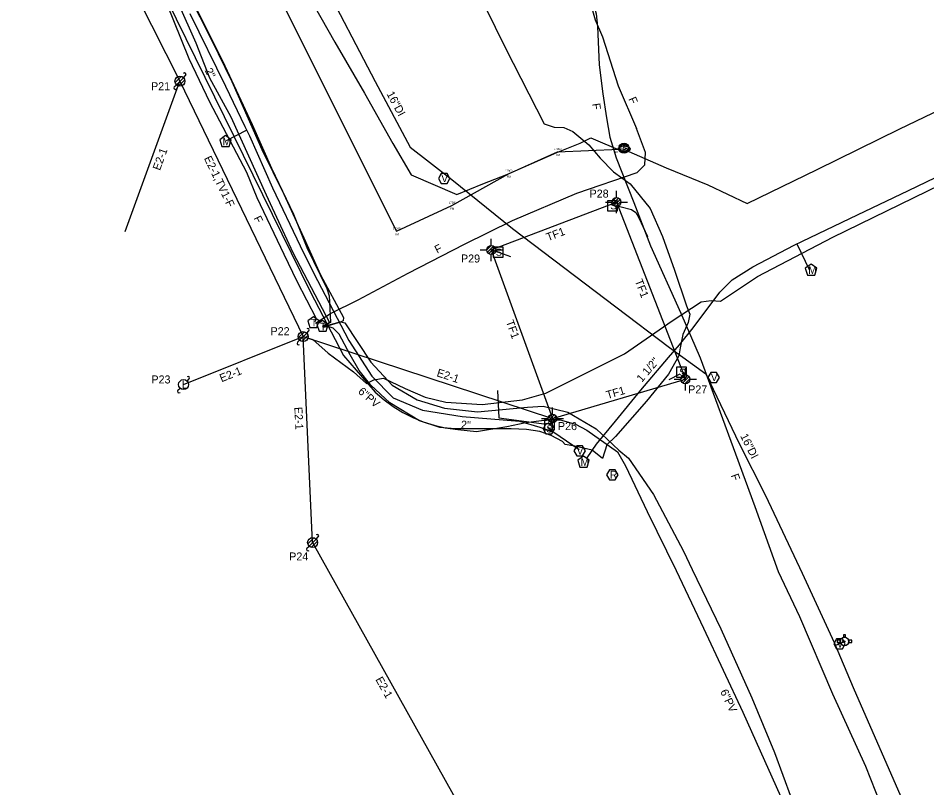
# Model space of a CAD drawing. Extents: x 1614474 to 1865144, y 1098877 to 1212550.
# Drawn here: x 1755531 to 1755984.8, y 1168201.1 to 1168585.7 of the extents above; entities that cross this region are included whole.
import ezdxf

# ---------------------------------------------------------------- set-up
doc = ezdxf.new("R2010")
doc.units = 0
for name, color, linetype in [('RD_EX_SU_H2O', 7, 'Continuous'), ('RD_EX_SU_Ovhd', 7, 'Continuous'), ('RD_EX_SU_Pole', 7, 'Continuous'), ('RD_EX_SU_Sewer', 7, 'Continuous'), ('RD_EX_SU_Telecom', 7, 'Continuous'), ('RD_EX_SU_Trfc', 7, 'Continuous'), ('RD_EX_SU_TX_H2O', 7, 'Continuous'), ('RD_EX_SU_TX_Pole', 7, 'Continuous'), ('RD_EX_SU_TX_Sewer', 7, 'Continuous'), ('RD_EX_SU_TX_Telecom', 7, 'Continuous'), ('RD_EX_UT_txCode', 7, 'Continuous'), ('RD_EX_VEG_txCode', 7, 'Continuous'), ('RD_SMD_Locator', 7, 'Continuous')]:
    doc.layers.add(name, color=color, linetype=linetype)

# ---------------------------------------------------------------- blocks, each defined once
blk = doc.blocks.new('SUE_SMH')
at = {"layer": 'RD_EX_SU_Sewer'}
blk.add_circle((0, 0), 2.5, dxfattribs=at)
blk.add_text('S', height=3.57, dxfattribs=at).set_placement((-1.1, -1.79))
blk = doc.blocks.new('SUE_WFH')
at = {"layer": 'RD_EX_SU_H2O'}
for p, q in [((-2.01, 0.6), (-3.65, 0.6)), ((-3.65, 0.6), (-3.65, -0.45)), ((-0.48, 3.38), (-0.48, 2.04)), ((0.57, 3.38), (-0.48, 3.38)), ((0.57, 2.02), (0.57, 3.38)), ((3.7, 0.6), (2.01, 0.6)), ((3.7, -0.45), (3.7, 0.6)), ((-3.65, -0.45), (-2.05, -0.45)), ((2.05, -0.45), (3.7, -0.45))]:
    blk.add_line(p, q, dxfattribs=at)
for radius in [2.1, 0.263]:
    blk.add_circle((0, 0), radius, dxfattribs=at)
for start, end in [(163.3387, 192.315), (74.2455, 103.2128), (347.685, 16.6613)]:
    blk.add_arc((0, 0), 2.1, start, end, dxfattribs=at)
blk = doc.blocks.new('SUE_WV')
at = {"layer": 'RD_EX_SU_H2O'}
blk.add_lwpolyline([(2.89, 0), (1.44, 2.5), (-1.44, 2.5), (-2.89, 0), (-1.44, -2.5), (1.44, -2.5)], close=True, dxfattribs=at)
blk.add_text('V', height=3.75, dxfattribs=at).set_placement((-1.43, -1.88))

msp = doc.modelspace()

# ---------------------------------------------------------------- linework, layer by layer
at = {"layer": 'RD_EX_SU_H2O'}
for p, q in [((1755635.04, 1168524.51), (1755645.11, 1168529.78)), ((1755919.85, 1168472.87), (1755926.01, 1168460.03)), ((1755943.15, 1168273.87), (1755939.17, 1168272.13))]:
    msp.add_line(p, q, dxfattribs=at)
for points in [[(1755385.42, 1169098.44), (1755401.32, 1169066.46), (1755415.89, 1169036.4), (1755422.95, 1169020.76), (1755426.26, 1169009.34), (1755463.14, 1168972.48), (1755499.82, 1168933.69), (1755512.6, 1168909), (1755538.91, 1168856.4), (1755564.45, 1168803.54), (1755584.77, 1168764.26), (1755602.59, 1168754.78), (1755634.52, 1168695.09), (1755648.65, 1168669.94), (1755682.22, 1168606.15), (1755709.26, 1168554.06), (1755726.87, 1168521.3)], [(1755616.79, 1168588.07), (1755634.63, 1168551.68), (1755644.21, 1168531.62), (1755646.53, 1168526.85), (1755658.08, 1168500.86), (1755671.83, 1168471.89), (1755678.5, 1168458.37), (1755696.16, 1168424.57), (1755707.62, 1168406.78), (1755718.29, 1168395.98), (1755732.94, 1168389.76), (1755752.68, 1168386.64), (1755781.36, 1168384.25), (1755791.61, 1168381.24), (1755798.5, 1168378.79), (1755811.16, 1168370.13)], [(1755726.87, 1168521.3), (1755747.63, 1168505.06), (1755777.82, 1168480.62), (1755829.49, 1168441.52), (1755856.27, 1168421.17), (1755874.43, 1168407.88), (1755891.14, 1168373.18), (1755904.2, 1168347.14)], [(1755815.25, 1168366.07), (1755819.84, 1168372.8), (1755829.29, 1168384.27), (1755841.99, 1168399.77), (1755855.87, 1168416.06), (1755861.36, 1168422.49), (1755868.12, 1168430.87), (1755881.49, 1168448.74), (1755887.6, 1168454.86), (1755897.94, 1168461.44), (1755918.53, 1168472.25), (1755922.78, 1168474.28), (1755950.16, 1168487.37), (1755975.7, 1168499.57), (1756003.04, 1168512.76)], [(1755904.2, 1168347.14), (1755922.61, 1168308.3), (1755938.52, 1168273.68), (1755948, 1168251.19), (1755972.99, 1168194.09), (1755995.27, 1168140.77), (1756050.84, 1167988.86), (1756081.08, 1167905.61), (1756101.58, 1167855.44), (1756116.98, 1167816.66), (1756140.78, 1167753.22), (1756156.44, 1167713.09), (1756172.97, 1167668.41), (1756185.91, 1167635.6), (1756220.9, 1167543.58)]]:
    msp.add_lwpolyline(points, dxfattribs=at)
for points in [[(1755634.55, 1168527.07), (1755631.64, 1168524.96), (1755632.75, 1168521.55), (1755636.34, 1168521.55), (1755637.45, 1168524.96)], [(1755746.64, 1168505.62), (1755745.2, 1168508.12), (1755742.31, 1168508.12), (1755740.87, 1168505.62), (1755742.31, 1168503.12), (1755745.2, 1168503.12)], [(1755927.04, 1168462.79), (1755924.14, 1168460.69), (1755925.25, 1168457.28), (1755928.83, 1168457.28), (1755929.94, 1168460.69)], [(1755881.31, 1168406.21), (1755879.87, 1168408.71), (1755876.98, 1168408.71), (1755875.54, 1168406.21), (1755876.98, 1168403.71), (1755879.87, 1168403.71)], [(1755814.29, 1168369.49), (1755812.85, 1168371.99), (1755809.96, 1168371.99), (1755808.52, 1168369.49), (1755809.96, 1168366.99), (1755812.85, 1168366.99)], [(1755813.37, 1168366.89), (1755810.46, 1168364.79), (1755811.57, 1168361.38), (1755815.16, 1168361.38), (1755816.27, 1168364.79)]]:
    msp.add_lwpolyline(points, close=True, dxfattribs=at)
at = {"layer": 'RD_EX_SU_Ovhd'}
for p, q in [((1755499.08, 1168777.54), (1755611.8, 1168554.19)), ((1755584.39, 1168479.07), (1755611.8, 1168554.19)), ((1755611.8, 1168554.19), (1755673.33, 1168426.55)), ((1755767.32, 1168469.86), (1755829.82, 1168493.82)), ((1755829.82, 1168493.82), (1755864.24, 1168405.22)), ((1755767.32, 1168469.86), (1755797.9, 1168385.65)), ((1755613.6, 1168402.59), (1755673.33, 1168426.55)), ((1755678.06, 1168323.63), (1755673.33, 1168426.55)), ((1755673.33, 1168426.55), (1755797.9, 1168385.65)), ((1755797.9, 1168385.65), (1755864.24, 1168405.22)), ((1755678.06, 1168323.63), (1755772.38, 1168154.45))]:
    msp.add_line(p, q, dxfattribs=at)
at = {"layer": 'RD_EX_SU_Pole'}
for p, q in [((1755609.38, 1168553.54), (1755612.45, 1168556.6)), ((1755610.03, 1168552.42), (1755613.57, 1168555.95)), ((1755611.15, 1168551.77), (1755614.21, 1168554.83)), ((1755613.57, 1168555.95), (1755614.63, 1168557.01)), ((1755608.97, 1168551.36), (1755610.03, 1168552.42)), ((1755827.61, 1168493.96), (1755829.69, 1168496.04)), ((1755827.86, 1168492.8), (1755830.85, 1168495.78)), ((1755829.82, 1168496.04), (1755829.82, 1168499.35)), ((1755824.3, 1168493.82), (1755827.6, 1168493.82)), ((1755828.51, 1168492.04), (1755831.61, 1168495.13)), ((1755829.52, 1168491.63), (1755832.02, 1168494.12)), ((1755829.82, 1168488.3), (1755829.82, 1168491.61)), ((1755832.04, 1168493.82), (1755835.34, 1168493.82)), ((1755767.32, 1168472.08), (1755767.32, 1168475.39)), ((1755761.8, 1168469.86), (1755765.11, 1168469.86)), ((1755765.11, 1168469.99), (1755767.2, 1168472.07)), ((1755765.36, 1168468.83), (1755768.36, 1168471.82)), ((1755766.01, 1168468.07), (1755769.12, 1168471.16)), ((1755767.02, 1168467.66), (1755769.52, 1168470.15)), ((1755769.54, 1168469.86), (1755772.85, 1168469.86)), ((1755767.32, 1168464.33), (1755767.32, 1168467.64)), ((1755670.91, 1168425.91), (1755673.98, 1168428.97)), ((1755671.56, 1168424.79), (1755675.1, 1168428.32)), ((1755675.1, 1168428.32), (1755676.16, 1168429.38)), ((1755670.5, 1168423.73), (1755671.56, 1168424.79)), ((1755672.68, 1168424.14), (1755675.74, 1168427.2)), ((1755864.24, 1168407.44), (1755864.24, 1168410.75)), ((1755615.37, 1168404.35), (1755616.43, 1168405.42)), ((1755858.72, 1168405.22), (1755862.03, 1168405.22)), ((1755862.03, 1168405.35), (1755864.12, 1168407.43)), ((1755862.28, 1168404.19), (1755865.28, 1168407.18)), ((1755862.93, 1168403.43), (1755866.04, 1168406.52)), ((1755863.94, 1168403.02), (1755866.44, 1168405.51)), ((1755866.46, 1168405.22), (1755869.77, 1168405.22)), ((1755610.77, 1168399.76), (1755611.83, 1168400.82)), ((1755864.24, 1168399.69), (1755864.24, 1168403)), ((1755795.69, 1168385.78), (1755797.77, 1168387.86)), ((1755795.94, 1168384.62), (1755798.93, 1168387.61)), ((1755796.59, 1168383.86), (1755799.69, 1168386.95)), ((1755797.9, 1168387.87), (1755797.9, 1168391.18)), ((1755792.38, 1168385.65), (1755795.68, 1168385.65)), ((1755797.6, 1168383.45), (1755800.1, 1168385.94)), ((1755797.9, 1168380.12), (1755797.9, 1168383.43)), ((1755800.12, 1168385.65), (1755803.42, 1168385.65)), ((1755675.65, 1168322.99), (1755678.71, 1168326.05)), ((1755676.3, 1168321.87), (1755679.83, 1168325.41)), ((1755677.42, 1168321.22), (1755680.48, 1168324.29)), ((1755679.83, 1168325.41), (1755680.89, 1168326.47)), ((1755675.24, 1168320.81), (1755676.3, 1168321.87))]:
    msp.add_line(p, q, dxfattribs=at)
for centre, radius in [((1755611.8, 1168554.19), 2.5), ((1755829.82, 1168493.82), 2.22), ((1755767.32, 1168469.86), 2.22), ((1755673.33, 1168426.55), 2.5), ((1755613.6, 1168402.59), 2.5), ((1755864.24, 1168405.22), 2.22), ((1755797.9, 1168385.65), 2.22), ((1755678.07, 1168323.64), 2.5)]:
    msp.add_circle(centre, radius, dxfattribs=at)
for centre, start, end in [((1755614.1, 1168557.54), 315, 135), ((1755609.5, 1168550.83), 135, 315), ((1755675.63, 1168429.91), 315, 135), ((1755671.03, 1168423.2), 135, 315), ((1755615.9, 1168405.95), 315, 135), ((1755611.3, 1168399.23), 135, 315), ((1755680.36, 1168327), 315, 135), ((1755675.77, 1168320.28), 135, 315)]:
    msp.add_arc(centre, 0.75, start, end, dxfattribs=at)
at = {"layer": 'RD_EX_SU_Sewer'}
for points in [[(1755538.02, 1168731.98), (1755677.08, 1168448.83), (1755693.42, 1168417.12), (1755709.32, 1168398.86), (1755713.78, 1168394.98), (1755718.32, 1168391.64), (1755723.12, 1168388.68), (1755728.15, 1168386.12), (1755733.36, 1168383.98), (1755738.74, 1168382.28), (1755744.23, 1168381.02), (1755750.62, 1168380.15), (1755759.98, 1168379.15), (1755775.13, 1168381.6), (1755784.54, 1168383.67), (1755792.42, 1168384.71), (1755797.45, 1168385.03), (1755801.74, 1168384.97), (1755809.29, 1168382.85), (1755815.1, 1168379.89), (1755830.27, 1168368.97), (1755834.26, 1168361.92), (1755845.18, 1168339.2), (1755859.61, 1168309.77), (1755873.36, 1168280.81), (1755893.01, 1168238.82), (1755918.27, 1168182.4)], [(1755833.4, 1168520.19), (1755854.68, 1168510.84), (1755875.52, 1168502.34), (1755895.06, 1168493.1), (1755930.11, 1168510.09), (1755971.34, 1168530.46), (1756049.09, 1168567.75), (1756167.6, 1168625.42), (1756207.81, 1168645.15), (1756226.79, 1168655.14), (1756237.27, 1168663.29), (1756249.83, 1168676.69), (1756258.66, 1168686.07), (1756260.41, 1168686.42), (1756288.47, 1168691.24), (1756293.05, 1168692.1), (1756294.39, 1168670.91), (1756296.55, 1168641.01), (1756298.7, 1168612.4), (1756300.63, 1168584.8), (1756304.07, 1168543.33), (1756307.31, 1168500.11), (1756311.13, 1168456.78)], [(1755675.18, 1168598.54), (1755689.17, 1168573.75), (1755703.97, 1168548.28), (1755718.09, 1168523.12), (1755727.27, 1168507.43), (1755750.04, 1168497.58), (1755763.04, 1168502.91), (1755775.14, 1168507.49), (1755800.07, 1168518.6), (1755811.62, 1168523.3), (1755816.99, 1168525.81), (1755833.04, 1168519.03)]]:
    msp.add_lwpolyline(points, dxfattribs=at)
msp.add_lwpolyline([(1755830.66, 1168357.52), (1755829.22, 1168360.02), (1755826.33, 1168360.02), (1755824.88, 1168357.52), (1755826.33, 1168355.02), (1755829.22, 1168355.02)], close=True, dxfattribs=at)
msp.add_circle((1755833.67, 1168520.74), 2, dxfattribs=at)
msp.add_ellipse((1755833.72, 1168520.34), major_axis=(-3, 0), ratio=0.5, dxfattribs=at)
at = {"layer": 'RD_EX_SU_Telecom'}
for points in [[(1755590.16, 1169126.29), (1755590.98, 1169107.71), (1755588.59, 1169093.98), (1755585.74, 1169086.47), (1755598.29, 1169061.2), (1755650.69, 1168954.78), (1755669.04, 1168919.98), (1755680.52, 1168896.3), (1755696.94, 1168870.9), (1755720.15, 1168844.14), (1755735.51, 1168794.5), (1755736.19, 1168774.57), (1755740.79, 1168758.88), (1755761.5, 1168735.33), (1755775.66, 1168711.24), (1755791.36, 1168667.81), (1755799.39, 1168654.61), (1755819.15, 1168584.91), (1755822.92, 1168576.29), (1755830.76, 1168551.82), (1755839.8, 1168530.61)], [(1755643.16, 1168988.99), (1755650.24, 1168970.42), (1755659.27, 1168949.97), (1755675.7, 1168921.3), (1755696.74, 1168888.73), (1755711.98, 1168863.4), (1755726.14, 1168838.3), (1755741.49, 1168798.28), (1755756.63, 1168758.91), (1755772.29, 1168720.09), (1755790.19, 1168679.27), (1755805.71, 1168638.46), (1755819.76, 1168587.82), (1755820.42, 1168581.52)], [(1755512.1, 1168728.24), (1755525.71, 1168737.52), (1755529.7, 1168739.68), (1755534.51, 1168741.84), (1755538.4, 1168742.46), (1755542.64, 1168741.85), (1755545.72, 1168740.78), (1755547.74, 1168739.27), (1755552.53, 1168728.77), (1755563.81, 1168704.31), (1755586.05, 1168658.34), (1755599.42, 1168631.31), (1755616.67, 1168597.14), (1755633.05, 1168564.37), (1755647.91, 1168532.61), (1755657.47, 1168510.73), (1755668.47, 1168487.78), (1755675.2, 1168471.07), (1755685.09, 1168450.55), (1755686.31, 1168447), (1755686.46, 1168443.88), (1755687.07, 1168433.57), (1755682.96, 1168431.41)], [(1755737.87, 1168644.92), (1755774.46, 1168570.64), (1755793.8, 1168532.87), (1755798.73, 1168531.24), (1755803.48, 1168531.11), (1755808.03, 1168529.01), (1755816.1, 1168522.43), (1755821.75, 1168515.75), (1755828.3, 1168508.82), (1755836.59, 1168502.92), (1755846.59, 1168490.64), (1755852.89, 1168476.58), (1755858.89, 1168459.81), (1755864.75, 1168441.96), (1755866.44, 1168437.76), (1755865.72, 1168433.54), (1755862.91, 1168427.6), (1755861.7, 1168420.97), (1755860.93, 1168416.93), (1755855.87, 1168407.81), (1755844.79, 1168394.37), (1755829.28, 1168376.59), (1755825.07, 1168372.41), (1755822.91, 1168365.68), (1755817.74, 1168369.85), (1755809.06, 1168371.75), (1755804.23, 1168372.69), (1755802.82, 1168374.22), (1755797.14, 1168377.22), (1755791.58, 1168379.14), (1755784.84, 1168380.17), (1755777.16, 1168380.53), (1755749.1, 1168380.46), (1755741.68, 1168381.1), (1755731.52, 1168384.53), (1755716.59, 1168393.46), (1755707.1, 1168402.22), (1755701.25, 1168409.7), (1755696.77, 1168417.52), (1755691.3, 1168427.8), (1755688.36, 1168430.83), (1755685.79, 1168431.67), (1755683.46, 1168431.17)], [(1755610.47, 1168608.91), (1755627.34, 1168575.22), (1755637.64, 1168554.12), (1755652.77, 1168520.08), (1755663.73, 1168497.74), (1755674.59, 1168474.03), (1755682.07, 1168457.47), (1755693.44, 1168436.04), (1755693.38, 1168434.49), (1755692.39, 1168433.88), (1755683.15, 1168431.4)], [(1755601.28, 1168602.82), (1755616.31, 1168565.61), (1755626.54, 1168543.8), (1755645.11, 1168508.8), (1755650.21, 1168496.11), (1755663.64, 1168467.83), (1755670.15, 1168454.35), (1755679.81, 1168435.61), (1755679.25, 1168434)], [(1755610.86, 1168593.19), (1755619.66, 1168573.4), (1755626.6, 1168555.82), (1755637.26, 1168536.36), (1755654.8, 1168497.45), (1755668.14, 1168468.66), (1755686.47, 1168433.56), (1755682.82, 1168431.61)], [(1755820.42, 1168581.52), (1755821.25, 1168562.36), (1755823, 1168547.9), (1755824.82, 1168535.83), (1755826.58, 1168526.22), (1755829.64, 1168515.94), (1755838.44, 1168493.5), (1755846.87, 1168471.86), (1755861.95, 1168438.23), (1755871.65, 1168415.93), (1755889.34, 1168367.97), (1755898.9, 1168341.72)], [(1755679.58, 1168433.3), (1755687.03, 1168438.08), (1755700.87, 1168444.86), (1755725.73, 1168458.23), (1755753.87, 1168472.69), (1755777.85, 1168484.62), (1755809.97, 1168498.23), (1755840.19, 1168508.58), (1755844.04, 1168512.33), (1755844.37, 1168518.5), (1755839.8, 1168530.61)], [(1755674.42, 1168426.23), (1755678.17, 1168425.12), (1755685.87, 1168418.31), (1755698.42, 1168409.03), (1755704.98, 1168403.09), (1755708.6, 1168405.04), (1755713.44, 1168405.79), (1755724.28, 1168400.63), (1755734.34, 1168396.34), (1755744.65, 1168393.75), (1755762.76, 1168392.58), (1755782.9, 1168395.04), (1755794.58, 1168398.36), (1755833.79, 1168418), (1755857.65, 1168434.43), (1755872.17, 1168443.94), (1755877.09, 1168444.69), (1755881.84, 1168444.33), (1755900.35, 1168456.59), (1755937.92, 1168476.33), (1755964.85, 1168489.47), (1756005.15, 1168509.07)], [(1755683.09, 1168431.31), (1755692.17, 1168434), (1755694.1, 1168433.4), (1755707.11, 1168413.71), (1755717.73, 1168402.31), (1755730.31, 1168394.95), (1755743.9, 1168390.86), (1755760.42, 1168389), (1755785.37, 1168391.33), (1755793.2, 1168391.88), (1755805.48, 1168388.79), (1755819.73, 1168380.45), (1755830.93, 1168369.82), (1755835.84, 1168365.8), (1755848.29, 1168347.64), (1755863.29, 1168319.35), (1755867.59, 1168310.21)], [(1755898.9, 1168341.72), (1755910.59, 1168309.21), (1755921.23, 1168286.67), (1755937.77, 1168248.04), (1755954.25, 1168211.92), (1755964.15, 1168186.62)], [(1755867.59, 1168310.21), (1755881.89, 1168280.5), (1755897.42, 1168246.03), (1755908.8, 1168218.82), (1755921.3, 1168184.71), (1755928.36, 1168167.28), (1755939.17, 1168144.41), (1755964.51, 1168092.26), (1755967.52, 1168083.62), (1755974.77, 1168068.14), (1755981.19, 1168052.22), (1755980.43, 1168050.52), (1755973.2, 1168046.59)]]:
    msp.add_lwpolyline(points, dxfattribs=at)
for points in [[(1755678.47, 1168436.5), (1755675.62, 1168434.42), (1755676.71, 1168431.07), (1755680.24, 1168431.07), (1755681.33, 1168434.42)], [(1755683.05, 1168434.65), (1755680.19, 1168432.57), (1755681.28, 1168429.22), (1755684.81, 1168429.22), (1755685.9, 1168432.57)]]:
    msp.add_lwpolyline(points, close=True, dxfattribs=at)
at = {"layer": 'RD_EX_SU_Trfc'}
for p, q in [((1755829.87, 1168493.72), (1755828.09, 1168492.81)), ((1755861.54, 1168407.8), (1755855.92, 1168404.89)), ((1755864.26, 1168405.59), (1755862.85, 1168408.31)), ((1755797.33, 1168383.16), (1755797.76, 1168385.17))]:
    msp.add_line(p, q, dxfattribs=at)
for points in [[(1755830.41, 1168494.45), (1755825.41, 1168494.45), (1755825.41, 1168489.45), (1755830.41, 1168489.45)], [(1755773.19, 1168471.27), (1755768.2, 1168471.27), (1755768.2, 1168466.27), (1755773.19, 1168466.27)], [(1755864.85, 1168411.29), (1755859.85, 1168411.29), (1755859.85, 1168406.29), (1755864.85, 1168406.29)], [(1755798.91, 1168380.45), (1755797.47, 1168382.95), (1755794.58, 1168382.95), (1755793.14, 1168380.45), (1755794.58, 1168377.95), (1755797.47, 1168377.95)], [(1755798.83, 1168384.96), (1755793.83, 1168384.96), (1755793.83, 1168379.96), (1755798.83, 1168379.96)]]:
    msp.add_lwpolyline(points, close=True, dxfattribs=at)
for points in [[(1755828.57, 1168492.19), (1755832.25, 1168491.47), (1755837.41, 1168490.1), (1755839.43, 1168488.53), (1755841, 1168485.91), (1755845.32, 1168476.65)], [(1755767.53, 1168469.73), (1755771.36, 1168468.58), (1755776.92, 1168466.63)], [(1755770.34, 1168399.61), (1755771.12, 1168385.96), (1755794.96, 1168382.77)]]:
    msp.add_lwpolyline(points, dxfattribs=at)
at = {"layer": 'RD_EX_SU_TX_Sewer'}
msp.add_lwpolyline([(1755549.64, 1168737.44), (1755557.76, 1168741.71), (1755578.58, 1168752.1), (1755582.79, 1168753.78), (1755719.92, 1168479.2), (1755747.6, 1168492), (1755775.92, 1168507.94), (1755800.38, 1168518.87), (1755831.36, 1168520.25)], dxfattribs=at)
at = {"layer": 'RD_SMD_Locator'}
for centre in [(1755800.38, 1168518.87), (1755831.36, 1168520.25), (1755775.92, 1168507.94), (1755747.6, 1168492), (1755719.92, 1168479.2)]:
    msp.add_circle(centre, 0.001, dxfattribs=at)

# ---------------------------------------------------------------- block references
at = {"layer": 'RD_EX_SU_H2O'}
for name, p in [('SUE_WV', (1755941.23, 1168273.04)), ('SUE_WFH', (1755943.71, 1168274.21))]:
    msp.add_blockref(name, p, dxfattribs=at)
at = {"layer": 'RD_EX_SU_Sewer'}
msp.add_blockref('SUE_SMH', (1755833.61, 1168520.73), dxfattribs=at)

# ---------------------------------------------------------------- texts
at = {"layer": 'RD_EX_SU_H2O'}
for s, p in [('M', (1755633.11, 1168522.15)), ('V', (1755742.32, 1168503.75)), ('M', (1755925.61, 1168457.87)), ('V', (1755876.99, 1168404.33)), ('V', (1755809.97, 1168367.61)), ('M', (1755811.93, 1168361.97))]:
    msp.add_text(s, height=3.75, dxfattribs=at).set_placement(p)
at = {"layer": 'RD_EX_SU_Ovhd'}
for s, rotation, p in [('E2-1', 69.955, (1755601.8, 1168509.29)), ('E2-1,TV1-F', 295.7388, (1755623.7, 1168515.68)), ('TF1', 20.9796, (1755795.66, 1168474.18)), ('TF1', 291.2317, (1755838.91, 1168454.39)), ('TF1', 289.9557, (1755774.5, 1168434.02)), ('E2-1', 21.865, (1755632.57, 1168403.73)), ('E2-1', 341.8207, (1755739.73, 1168406.85)), ('TF1', 16.435, (1755825.35, 1168395.32)), ('E2-1', 272.63, (1755668.94, 1168391.32)), ('E2-1', 299.1412, (1755709.32, 1168255.24))]:
    msp.add_text(s, height=4, rotation=rotation, dxfattribs=at).set_placement(p)
at = {"layer": 'RD_EX_SU_Pole'}
msp.add_text('L', height=4, dxfattribs=at).set_placement((1755612.74, 1168400.59))
at = {"layer": 'RD_EX_SU_Sewer'}
for s, height, p in [('ARV', 1.5, (1755831.78, 1168519.59)), ('S', 2.5, (1755832.64, 1168519.56)), ('R', 4, (1755826.43, 1168355.52))]:
    msp.add_text(s, height=height, dxfattribs=at).set_placement(p)
at = {"layer": 'RD_EX_SU_Telecom'}
for p in [(1755677.22, 1168431.62), (1755681.79, 1168429.77)]:
    msp.add_text('T', height=3.75, dxfattribs=at).set_placement(p)
at = {"layer": 'RD_EX_SU_Trfc'}
for p in [(1755826.73, 1168490.18), (1755769.51, 1168467), (1755861.16, 1168407.02), (1755794.84, 1168378.68), (1755795.15, 1168380.7)]:
    msp.add_text('S', height=3.53, dxfattribs=at).set_placement(p)
at = {"layer": 'RD_EX_SU_TX_H2O'}
for s, rotation, p in [('2"', 296.1172, (1755624.06, 1168559.61)), ('16"DI', 298.2548, (1755714.87, 1168547.86)), ('1 1/2"', 49.5575, (1755842.5, 1168403.45)), ('2"', 355.2555, (1755752, 1168380.67)), ('16"DI', 296.6423, (1755891.51, 1168376.89))]:
    msp.add_text(s, height=4, rotation=rotation, dxfattribs=at).set_placement(p)
at = {"layer": 'RD_EX_SU_TX_Pole'}
for s, p in [('P21', (1755597.37, 1168549.68)), ('P28', (1755816.4, 1168496.03)), ('P29', (1755752.18, 1168463.6)), ('P22', (1755657.05, 1168427.28)), ('P23', (1755597.55, 1168403.16)), ('P27', (1755865.66, 1168398.19)), ('P26', (1755800.6, 1168379.84)), ('P24', (1755666.37, 1168314.7))]:
    msp.add_text(s, height=4, dxfattribs=at).set_placement(p)
at = {"layer": 'RD_EX_SU_TX_Sewer'}
for rotation, p in [(318.9697, (1755700.44, 1168398.63)), (295.0775, (1755881.52, 1168249.22))]:
    msp.add_text('6"PV', height=4, rotation=rotation, dxfattribs=at).set_placement(p)
at = {"layer": 'RD_EX_SU_TX_Telecom'}
for rotation, p in [(293.0865, (1755835.7, 1168545.33)), (278.5731, (1755817.69, 1168542.91)), (295.4034, (1755648.47, 1168485.79)), (27.2124, (1755740.28, 1168467.96)), (289.9985, (1755886.87, 1168357.21))]:
    msp.add_text('F', height=4, rotation=rotation, dxfattribs=at).set_placement(p)
at = {"layer": 'RD_EX_UT_txCode'}
for s, p in [('17085', (1755831.83, 1168521.74)), ('17086', (1755831.87, 1168521.34)), ('SMH', (1755832.38, 1168518.74)), ('SAR', (1755832.46, 1168518.34))]:
    msp.add_text(s, height=1, dxfattribs=at).set_placement(p)
at = {"layer": 'RD_EX_VEG_txCode'}
for s, p in [('17083', (1755798.55, 1168519.87)), ('EL*FM', (1755829.23, 1168518.25)), ('17084', (1755829.52, 1168521.25)), ('FM', (1755799.57, 1168516.87)), ('17082', (1755774.08, 1168508.94)), ('FM', (1755775.1, 1168505.94)), ('17081', (1755746.05, 1168493)), ('FM', (1755746.78, 1168490)), ('17080', (1755718.05, 1168480.2)), ('FM', (1755719.1, 1168477.2))]:
    msp.add_text(s, height=1, dxfattribs=at).set_placement(p)

doc.saveas('drawing.dxf')
